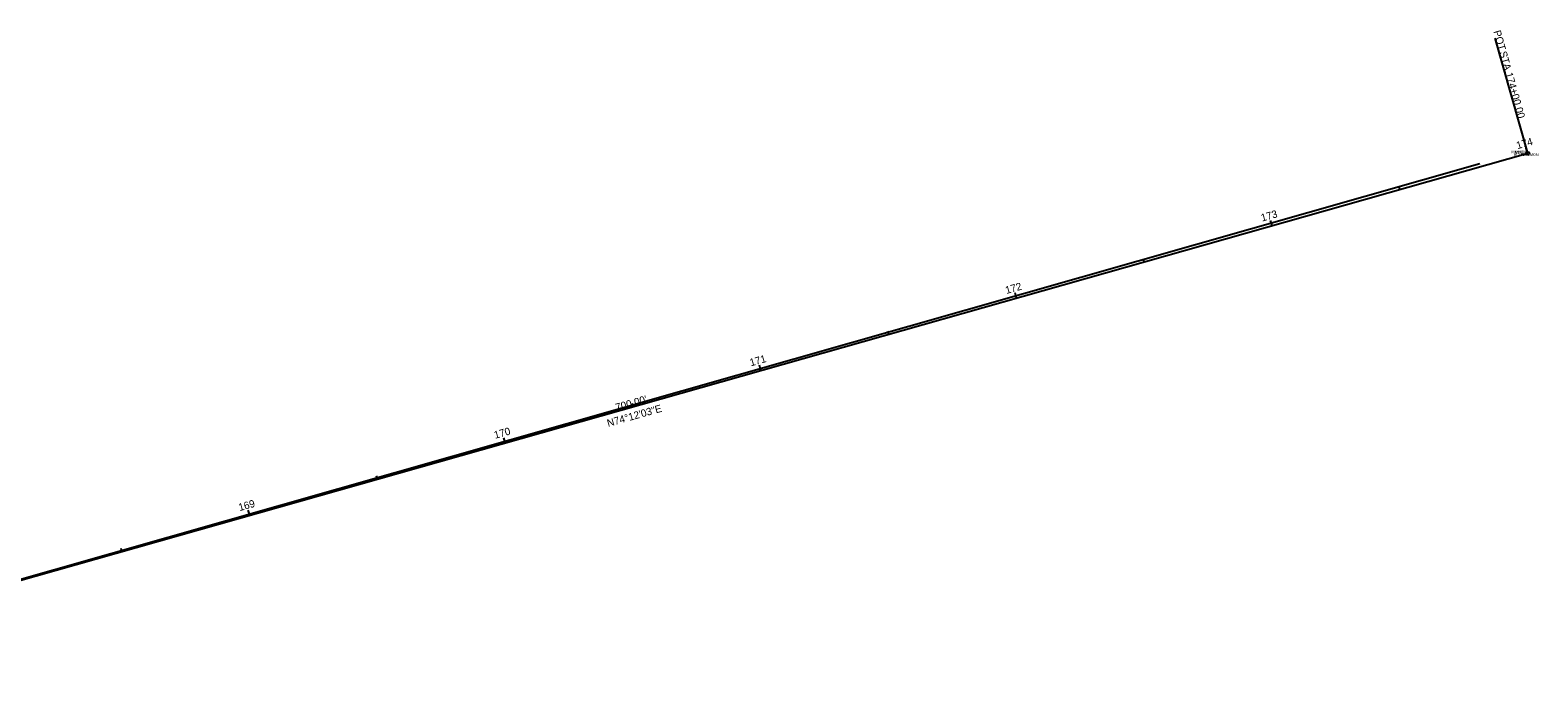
# Model space of a CAD drawing. Extents: x 2272920 to 2277360, y 743591 to 745058.
# Drawn here: x 2276793 to 2277360, y 744404 to 744646 of the extents above; entities that cross this region are included whole.
import ezdxf

# ---------------------------------------------------------------- set-up
doc = ezdxf.new("R2010")
doc.units = 0
for name, color, linetype in [('GE_X_Alignment', 7, 'Continuous'), ('GE_X_Alignment_100_Bearings', 7, 'Continuous'), ('GE_X_Alignment_100_Cardinal_Points', 7, 'Continuous'), ('GE_X_Alignment_100_Distances', 7, 'Continuous'), ('GE_X_Alignment_100_Stations', 7, 'Continuous'), ('SC_Scratch1', 7, 'Continuous'), ('SV_X_Text_Comment', 7, 'Continuous'), ('SV_X_Text_Elevation', 7, 'Continuous'), ('SV_X_Text_Name', 7, 'Continuous')]:
    doc.layers.add(name, color=color, linetype=linetype)

msp = doc.modelspace()

# ---------------------------------------------------------------- linework, layer by layer
at = {"layer": 'GE_X_Alignment'}
msp.add_line((2276682.83, 744409.06), (2277356.39, 744599.64), dxfattribs=at)
at = {"layer": 'GE_X_Alignment_100_Cardinal_Points'}
msp.add_line((2277356.39, 744599.64), (2277344.14, 744642.94), dxfattribs=at)
msp.add_circle((2277356.39, 744599.64), 0.6, dxfattribs=at)
at = {"layer": 'GE_X_Alignment_100_Stations'}
for p, q in [((2277356.38, 744599.64), (2277355.84, 744601.57)), ((2277308.27, 744586.03), (2277307.95, 744587.18)), ((2277260.16, 744572.42), (2277259.62, 744574.34)), ((2277212.05, 744558.8), (2277211.72, 744559.96)), ((2277163.94, 744545.19), (2277163.4, 744547.11)), ((2277115.83, 744531.58), (2277115.5, 744532.73)), ((2277067.72, 744517.96), (2277067.17, 744519.89)), ((2277019.61, 744504.35), (2277019.28, 744505.5)), ((2276971.5, 744490.74), (2276970.95, 744492.66)), ((2276923.38, 744477.12), (2276923.06, 744478.28)), ((2276875.27, 744463.51), (2276874.73, 744465.43)), ((2276827.16, 744449.9), (2276826.84, 744451.05))]:
    msp.add_line(p, q, dxfattribs=at)
at = {"layer": 'SC_Scratch1'}
msp.add_line((2276665.1, 744404.26), (2277338.38, 744595.82), dxfattribs=at)

# ---------------------------------------------------------------- texts
at = {"layer": 'GE_X_Alignment_100_Bearings'}
msp.add_text('N74°12\'03"E', height=2.8, rotation=15.7992, dxfattribs=at).set_placement((2277010.22, 744496.71))
at = {"layer": 'GE_X_Alignment_100_Cardinal_Points'}
for s, p in [('POT', (2277343.46, 744645.46)), (' STA. ', (2277345.4, 744638.6)), ('174+00.00', (2277347.94, 744629.63))]:
    msp.add_text(s, height=2.8, rotation=285.7992, dxfattribs=at).set_placement(p)
at = {"layer": 'GE_X_Alignment_100_Distances'}
msp.add_text("700.00'", height=2.8, rotation=15.7992, dxfattribs=at).set_placement((2277013.41, 744502.63))
at = {"layer": 'GE_X_Alignment_100_Stations'}
for s, p in [('174', (2277352.55, 744601.16)), ('173', (2277256.4, 744573.95)), ('172', (2277160.17, 744546.72)), ('171', (2277063.94, 744519.49)), ('170', (2276967.67, 744492.25)), ('169', (2276871.49, 744465.04))]:
    msp.add_text(s, height=2.8, rotation=15.7992, dxfattribs=at).set_placement(p)
at = {"layer": 'SV_X_Text_Comment'}
for p in [(2277356.22, 744598.6), (2277356.23, 744598.6)]:
    msp.add_text('CMON', height=1, dxfattribs=at).set_placement(p)
at = {"layer": 'SV_X_Text_Elevation'}
for s, p in [('913.810', (2277351.11, 744598.6)), ('913.789', (2277351.15, 744598.6))]:
    msp.add_text(s, height=1, dxfattribs=at).set_placement(p)
at = {"layer": 'SV_X_Text_Name'}
for s, p in [('MN103-1', (2277350.3, 744599.6)), ('MN103', (2277351.61, 744599.6))]:
    msp.add_text(s, height=1, dxfattribs=at).set_placement(p)

doc.saveas('drawing.dxf')
